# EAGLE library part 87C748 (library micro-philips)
8051 -comabtible 8bit Microcontroller
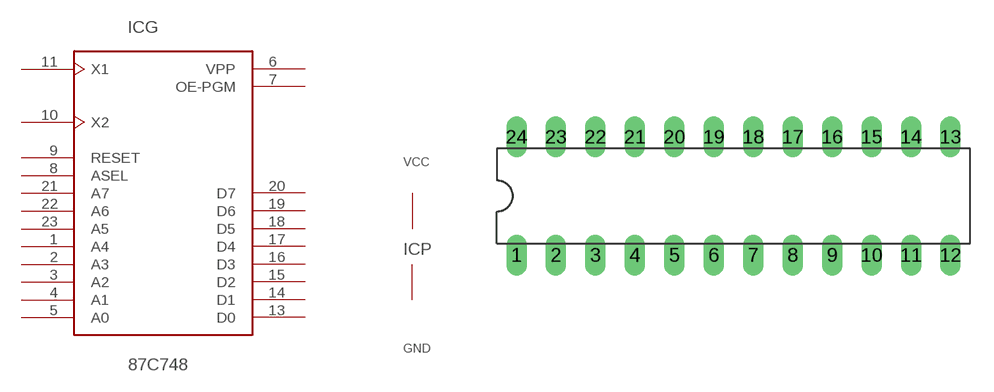
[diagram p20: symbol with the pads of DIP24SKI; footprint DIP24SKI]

Designator prefix IC; gates G=8XC748 P=PWR2

## 87C748 (OC_FARNELL: unknown; OC_NEWARK: unknown)  [DIP24SKI]
1  G:A4  out
2  G:A3  out
3  G:A2  out
4  G:A1  out
5  G:A0  out
6  G:VPP  pwr
7  G:OE-PGM  in
8  G:ASEL  out
9  G:RESET  in
10  G:X2  in
11  G:X1  in
12  P:GND  pwr
13  G:D0  hiz
14  G:D1  hiz
15  G:D2  hiz
16  G:D3  hiz
17  G:D4  hiz
18  G:D5  hiz
19  G:D6  hiz
20  G:D7  hiz
21  G:A7  out
22  G:A6  out
23  G:A5  out
24  P:VCC  pwr

## Footprint DIP24SKI (pad centres in mm)
Dual In Line
drill 0.813 pad 1.27 long: 1 -11.43,-3.81; 2 -8.89,-3.81; 3 -6.35,-3.81; 4 -3.81,-3.81; 5 -1.27,-3.81; 6 1.27,-3.81; 7 3.81,-3.81; 8 6.35,-3.81; 9 8.89,-3.81; 10 11.43,-3.81; 11 13.97,-3.81; 12 16.51,-3.81; 13 16.51,3.81; 14 13.97,3.81; 15 11.43,3.81; 16 8.89,3.81; 17 6.35,3.81; 18 3.81,3.81; 19 1.27,3.81; 20 -1.27,3.81; 21 -3.81,3.81; 22 -6.35,3.81; 23 -8.89,3.81; 24 -11.43,3.81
